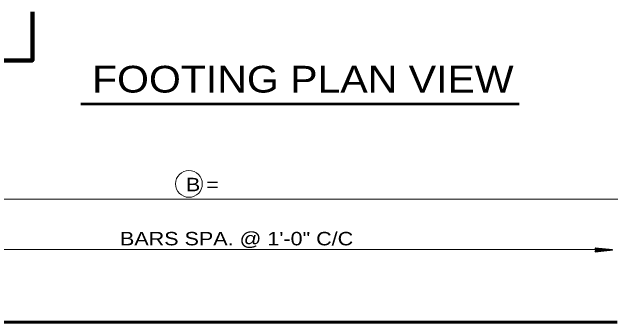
# Model space of a CAD drawing. Extents: x 14.14 to 17.34, y -1.61 to 0.38.
# Drawn here: x 14.6504 to 15.0222, y -0.4094 to -0.217 of the extents above; entities that cross this region are included whole.
import ezdxf

# ---------------------------------------------------------------- set-up
doc = ezdxf.new("R2010")
doc.units = 0
doc.header["$LTSCALE"] = 0.0033
doc.layers.add('1', color=7, linetype='Continuous', lineweight=40)

msp = doc.modelspace()

# ---------------------------------------------------------------- linework, layer by layer
at = {"layer": '1', "lineweight": 53}
msp.add_line((14.693167, -0.273917), (14.965833, -0.273917), dxfattribs=at)
at = {"layer": '1', "lineweight": 13}
for p, q in [((14.523417, -0.333083), (14.983333, -0.333083)), ((14.891583, -0.333083), (15.10575, -0.333083)), ((14.606333, -0.3645), (15.022333, -0.3645))]:
    msp.add_line(p, q, dxfattribs=at)
at = {"layer": '1', "lineweight": 35}
for p, q in [((15.013333, -0.363667), (15.021167, -0.364583)), ((15.013333, -0.363667), (15.021167, -0.364583)), ((15.013333, -0.36375), (15.021167, -0.364583)), ((15.013333, -0.363833), (15.021167, -0.364667)), ((15.013333, -0.363833), (15.021167, -0.364833)), ((15.013083, -0.364667), (15.023667, -0.364667)), ((15.01325, -0.365333), (15.020583, -0.364583)), ((15.013333, -0.3655), (15.020667, -0.364667)), ((15.013333, -0.365583), (15.020667, -0.364833)), ((15.013333, -0.36575), (15.020667, -0.364917))]:
    msp.add_line(p, q, dxfattribs=at)
at = {"layer": '1', "lineweight": 60}
for p, q in [((14.740667, -0.409417), (14.60275, -0.409417)), ((14.6465, -0.409417), (14.98225, -0.409417)), ((14.888667, -0.409417), (15.026583, -0.409417))]:
    msp.add_line(p, q, dxfattribs=at)
at = {"layer": '1', "lineweight": 90}
msp.add_lwpolyline([(14.663167, -0.217), (14.663167, -0.247083), (14.6215, -0.247083)], dxfattribs=at)
at = {"layer": '1', "lineweight": 35}
for points in [[(15.013083, -0.363583), (15.023667, -0.364667), (15.013083, -0.365833), (15.013667, -0.364667)], [(15.013833, -0.364583), (15.0185, -0.3645), (15.0185, -0.364583), (15.017583, -0.364583), (15.013833, -0.3645), (15.016833, -0.364417), (15.013667, -0.364333), (15.015917, -0.36425), (15.013667, -0.364167), (15.017167, -0.364417), (15.021833, -0.364583), (15.020917, -0.364833), (15.022167, -0.364833), (15.013833, -0.364833), (15.01625, -0.365), (15.013667, -0.365), (15.019, -0.364583), (15.013667, -0.36525)]]:
    msp.add_lwpolyline(points, close=True, dxfattribs=at)
msp.add_lwpolyline([(15.013833, -0.364583), (15.013417, -0.363833), (15.013667, -0.364083), (15.013833, -0.364417), (15.014083, -0.364333), (15.013917, -0.364), (15.01375, -0.36475), (15.013583, -0.36525), (15.013333, -0.365667)], dxfattribs=at)
at = {"layer": '1', "lineweight": 13}
msp.add_circle((14.760417, -0.323667), 0.008333, dxfattribs=at)

# ---------------------------------------------------------------- texts
at = {"layer": '1'}
for s, height, width, p in [('FOOTING PLAN VIEW', 0.01658, 1.15, (14.700167, -0.267)), ('B =      ', 0.008334, 1.2, (14.758583, -0.32825)), ('BARS SPA. @ 1\'-0" C/C', 0.008334, 1.2, (14.717583, -0.361833))]:
    msp.add_text(s, height=height, dxfattribs=dict(at, width=width)).set_placement(p)

doc.saveas('drawing.dxf')
